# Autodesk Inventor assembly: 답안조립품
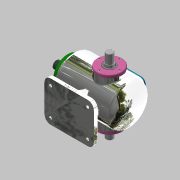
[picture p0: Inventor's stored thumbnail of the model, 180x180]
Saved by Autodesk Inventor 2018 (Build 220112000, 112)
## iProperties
Created: 2021-11
Part Number: 답안조립품
Material: 일반
Document SubType Name: Assembly
Designer: home
Author: home
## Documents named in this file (14)
- C:\Users\home\Desktop\711106V1035\답안조립품.iam
- C:\Users\home\Desktop\711106V1035\본체.ipt
- C:\Users\home\Desktop\711106V1035\베어링 6205.ipt
- 베어링 6205.ipt
- C:\Users\home\Desktop\711106V1035\축 커버.ipt
- C:\Users\home\Desktop\711106V1035\오일실.ipt
- 오일실.ipt
- C:\Users\home\Desktop\711106V1035\슬라이드 커버.ipt
- C:\Users\home\Desktop\711106V1035\부시.ipt
- C:\Users\home\Desktop\711106V1035\편심축.ipt
- C:\Users\home\Desktop\711106V1035\슬라이드.ipt
- C:\Users\home\Desktop\711106V1035\상부커버.ipt
- C:\Users\home\Desktop\711106V1035\육각머리볼트 M4.ipt
- C:\Users\home\Desktop\711106V1035\볼트 M4x0.7.ipt
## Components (12 placed, 1 different names)
1. M4x0.7:9
2. M4x0.7:10
3. M4x0.7:11
4. M4x0.7:12
5. M4x0.7:1
6. M4x0.7:3
7. M4x0.7:4
8. M4x0.7:5
9. M4x0.7:2
10. M4x0.7:6
11. M4x0.7:7
12. M4x0.7:8
